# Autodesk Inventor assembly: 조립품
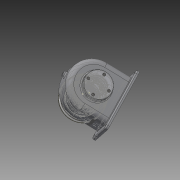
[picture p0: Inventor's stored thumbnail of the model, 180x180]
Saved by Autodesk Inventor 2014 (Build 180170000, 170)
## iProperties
Created: 2016-01
Part Number: 조립품
Document SubType Name: Assembly
Designer: KB20301
Author: KB20301
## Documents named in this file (16)
- C:\Users\KB20301\Desktop\460105V1026\460105V1026\조립품.iam
- C:\Users\KB20301\Desktop\460105V1026\1-본체.ipt
- C:\Users\KB20301\Desktop\460105V1026\460105V1026\V-벨트풀리.ipt
- C:\Users\KB20301\Desktop\460105V1026\460105V1026\뒤커버.ipt
- C:\Users\KB20301\Desktop\460105V1026\460105V1026\멈춤나사 - M4x10.ipt
- C:\Users\KB20301\Desktop\460105V1026\460105V1026\베어링 6203.ipt
- C:\Users\KB20301\Desktop\460105V1026\460105V1026\볼트 M3 x 8.ipt
- C:\Users\KB20301\Desktop\460105V1026\460105V1026\볼트 M3 x 10.ipt
- C:\Users\KB20301\Desktop\460105V1026\460105V1026\부시1.ipt
- C:\Users\KB20301\Desktop\460105V1026\460105V1026\부시2.ipt
- C:\Users\KB20301\Desktop\460105V1026\460105V1026\스퍼기어.ipt
- C:\Users\KB20301\Desktop\460105V1026\460105V1026\앞커버.ipt
- C:\Users\KB20301\Desktop\460105V1026\460105V1026\오일씰 28 40 8.ipt
- C:\Users\KB20301\Desktop\460105V1026\460105V1026\축.ipt
- C:\Users\KB20301\Desktop\460105V1026\460105V1026\키 - 5 x 5 x 18.ipt
- C:\Users\KB20301\Desktop\460105V1026\460105V1026\키 - 6 x 6 x 22.ipt
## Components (10 placed, 4 different names)
1. 1-본체:1
2. V-벨트풀리:1 — 플러쉬:1
3. ISO 4762 M3 x 8:1
4. ISO 4762 M3 x 8:2
5. ISO 4762 M3 x 8:3
6. ISO 4762 M3 x 8:4
7. ISO 4762 M3 x 10:1
8. ISO 4762 M3 x 10:2
9. ISO 4762 M3 x 10:3
10. ISO 4762 M3 x 10:4
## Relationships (1: Flush 1)
- 플러쉬:1 [Flush]: V-벨트풀리:1
